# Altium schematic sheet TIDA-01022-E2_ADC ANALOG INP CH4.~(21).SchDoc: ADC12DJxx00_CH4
size 431 x 279 mm; Date: Not shown in title block; ApprovedBy: Not shown in title block; CheckedBy: Not shown in title block; Author: Not shown in title block; CompanyName: Not shown in title block; DrawnBy: Avinash N; Engineer: Not shown in title block; Organization: Not shown in title block; Address1: Not shown in title block; Address2: Not shown in title block; Address3: Not shown in title block; Address4: Not shown in title block; DocumentNumber: 1; Revision: Use project parameter SCH_Rev; SheetNumber: 5; SheetTotal: 26; PageSetup: Record=PageOptions¦CenterHorizontal=True¦CenterVertical=True¦PrintScale=1.00¦XCorrection=1.00¦YCorrection=1.00¦PrintKind=0¦BorderSize=5000000¦LeftOffset=0¦BottomOffset=0¦Orientation=2¦PaperLength=1000¦PaperWidth=1000¦Scale=100¦PaperSource=15¦PrintQuality=600¦MediaType=1¦DitherType=10¦PaperKind=Letter¦PrintScaleMode=1
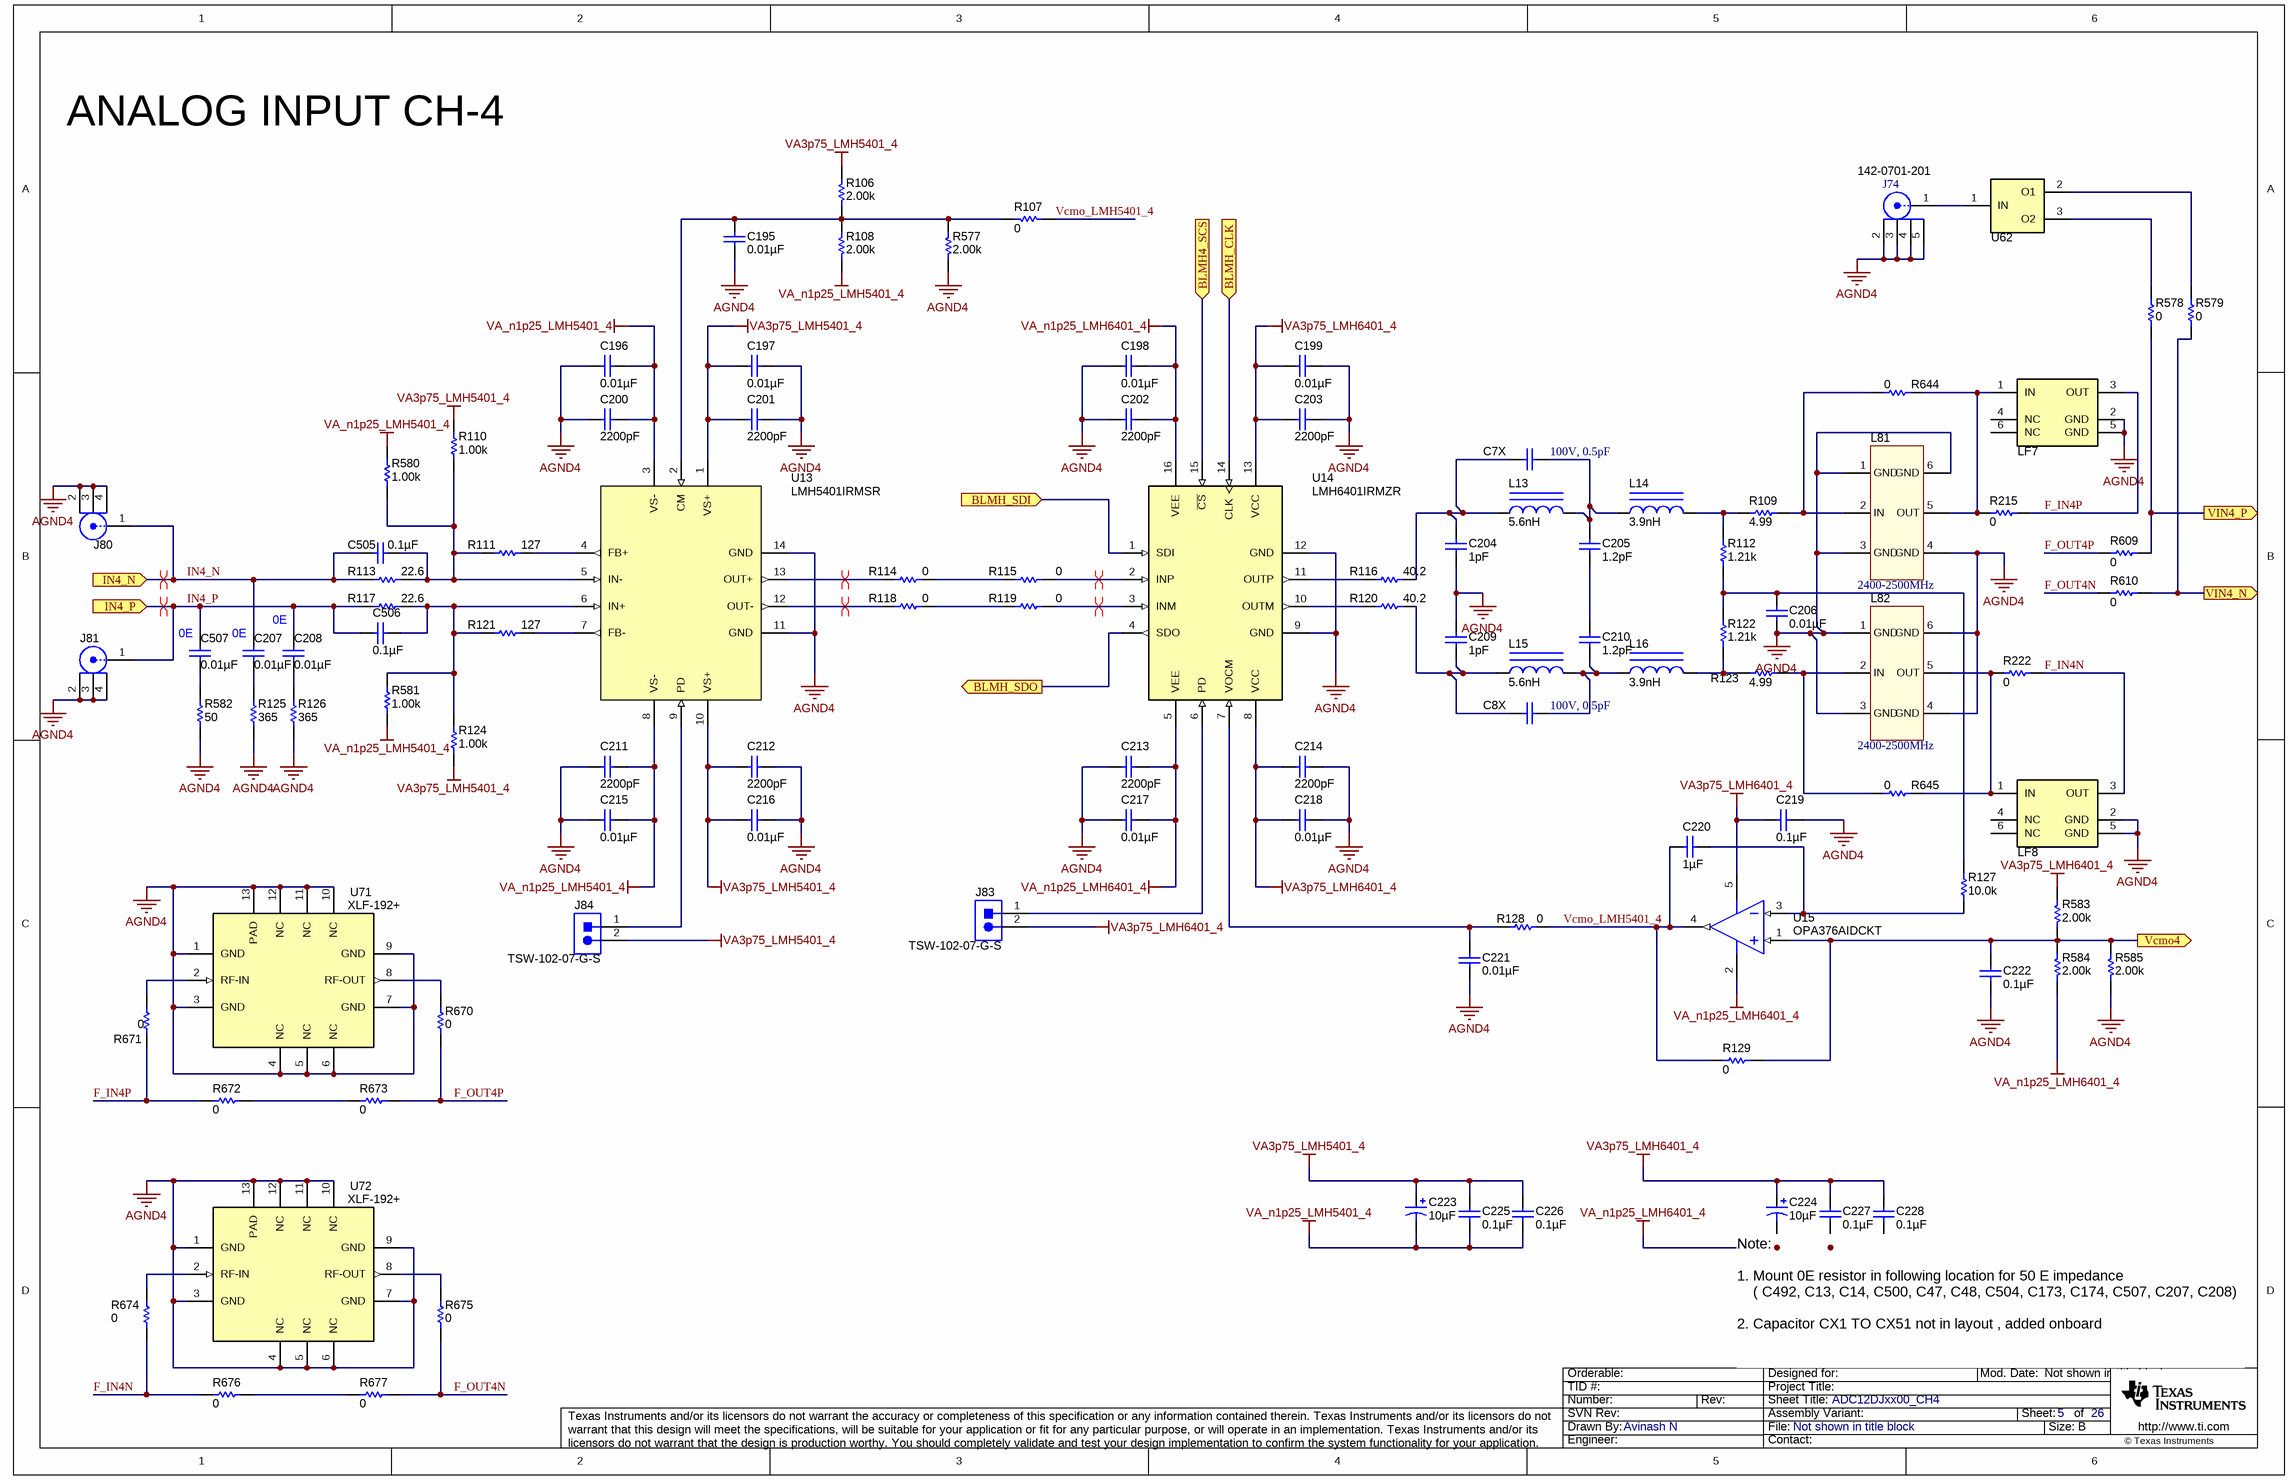
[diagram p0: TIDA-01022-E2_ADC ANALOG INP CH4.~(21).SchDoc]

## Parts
C7X  100V, 0.5pF  [0603_1.6x0.8x0.8mm_Reflow Soldering]
C8X  100V, 0.5pF  [0603_1.6x0.8x0.8mm_Reflow Soldering]
C195  ValueDisplayed: 0.01µF  [0402]  (hidden comment: GRM155R71E103KA01D)
C196  ValueDisplayed: 0.01µF  [0306]  (hidden comment: LLL185R71E103MA01L)
C197  ValueDisplayed: 0.01µF  [0306]  (hidden comment: LLL185R71E103MA01L)
C198  ValueDisplayed: 0.01µF  [0306]  (hidden comment: LLL185R71E103MA01L)
C199  ValueDisplayed: 0.01µF  [0306]  (hidden comment: LLL185R71E103MA01L)
C200  ValueDisplayed: 2200pF  [0306]  (hidden comment: LLL185R71H222MA01L)
C201  ValueDisplayed: 2200pF  [0306]  (hidden comment: LLL185R71H222MA01L)
C202  ValueDisplayed: 2200pF  [0306]  (hidden comment: LLL185R71H222MA01L)
C203  ValueDisplayed: 2200pF  [0306]  (hidden comment: LLL185R71H222MA01L)
C204  ValueDisplayed: 1pF  [0402]  (hidden comment: GRM1555C1H1R0CA01D)
C205  ValueDisplayed: 1.2pF  [0402]  (hidden comment: GRM1555C1H1R2BA01D)
C206  ValueDisplayed: 0.01µF  [0402]  (hidden comment: GRM155R71E103KA01D)
C207  ValueDisplayed: 0.01µF  [0402]  (hidden comment: GRM155R71E103KA01D)
C208  ValueDisplayed: 0.01µF  [0402]  (hidden comment: GRM155R71E103KA01D)
C209  ValueDisplayed: 1pF  [0402]  (hidden comment: GRM1555C1H1R0CA01D)
C210  ValueDisplayed: 1.2pF  [0402]  (hidden comment: GRM1555C1H1R2BA01D)
C211  ValueDisplayed: 2200pF  [0306]  (hidden comment: LLL185R71H222MA01L)
C212  ValueDisplayed: 2200pF  [0306]  (hidden comment: LLL185R71H222MA01L)
C213  ValueDisplayed: 2200pF  [0306]  (hidden comment: LLL185R71H222MA01L)
C214  ValueDisplayed: 2200pF  [0306]  (hidden comment: LLL185R71H222MA01L)
C215  ValueDisplayed: 0.01µF  [0306]  (hidden comment: LLL185R71E103MA01L)
C216  ValueDisplayed: 0.01µF  [0306]  (hidden comment: LLL185R71E103MA01L)
C217  ValueDisplayed: 0.01µF  [0306]  (hidden comment: LLL185R71E103MA01L)
C218  ValueDisplayed: 0.01µF  [0306]  (hidden comment: LLL185R71E103MA01L)
C219  ValueDisplayed: 0.1µF  [0402]  (hidden comment: C1005X5R1A104K050BA)
C220  ValueDisplayed: 1µF  [0603]  (hidden comment: C1608X5R1A105K080AC)
C221  ValueDisplayed: 0.01µF  [0402]  (hidden comment: GRM155R71E103KA01D)
C222  ValueDisplayed: 0.1µF  [0402]  (hidden comment: C1005X5R1A104K050BA)
C223  ValueDisplayed: 10µF  [3216-18]  (hidden comment: TPSA106K010R0900)
C224  ValueDisplayed: 10µF  [3216-18]  (hidden comment: TPSA106K010R0900)
C225  ValueDisplayed: 0.1µF  [0402]  (hidden comment: C1005X5R1A104K050BA)
C226  ValueDisplayed: 0.1µF  [0402]  (hidden comment: C1005X5R1A104K050BA)
C227  ValueDisplayed: 0.1µF  [0402]  (hidden comment: C1005X5R1A104K050BA)
C228  ValueDisplayed: 0.1µF  [0402]  (hidden comment: C1005X5R1A104K050BA)
C505  ValueDisplayed: 0.1µF  [0402]  (hidden comment: GRM155R71C104JA88D)
C506  ValueDisplayed: 0.1µF  [0402]  (hidden comment: GRM155R71C104JA88D)
C507  ValueDisplayed: 0.01µF  [0402]  (hidden comment: GRM155R71E103KA01D)
J74  142-0701-201  [Johnson_142-0701-20x]
J80  142-0771-831  [Johnson_142-0771-831]  (value not drawn)
J81  142-0771-831  [Johnson_142-0771-831]  (value not drawn)
J83  TSW-102-07-G-S  [TSW-102-07-G-S]
J84  TSW-102-07-G-S  [TSW-102-07-G-S]
L13  ValueDisplayed: 5.6nH  [LQW18A]  (hidden comment: LQW18AN5N6D10D)
L14  ValueDisplayed: 3.9nH  [0603HC]  (hidden comment: 0603HC-3N9XJLU)
L15  ValueDisplayed: 5.6nH  [LQW18A]  (hidden comment: LQW18AN5N6D10D)
L16  ValueDisplayed: 3.9nH  [0603HC]  (hidden comment: 0603HC-3N9XJLU)
L81  value 2400-2500MHz  [WE-LPF_0603]  (hidden comment: WE-LPF, 748112024)
L82  value 2400-2500MHz  [WE-LPF_0603]  (hidden comment: WE-LPF, 748112024)
LF7  LFL182G45TC3B746  [FIL_LFL18_TC1]  (value not drawn)
LF8  LFL182G45TC3B746  [FIL_LFL18_TC1]  (value not drawn)
R106  ValueDisplayed: 2.00k  [0402]  (hidden comment: CRCW04022K00FKED)
R107  ValueDisplayed: 0  [0402]  (hidden comment: CRCW04020000Z0ED)
R108  ValueDisplayed: 2.00k  [0402]  (hidden comment: CRCW04022K00FKED)
R109  ValueDisplayed: 4.99  [0402]  (hidden comment: CRCW04024R99FKED)
R110  ValueDisplayed: 1.00k  [0402]  (hidden comment: ERJ-2RKF1001X)
R111  ValueDisplayed: 127  [0402]  (hidden comment: CRCW0402127RFKED)
R112  ValueDisplayed: 1.21k  [0402]  (hidden comment: CRCW04021K21FKED)
R113  ValueDisplayed: 22.6  [0402]  (hidden comment: CRCW040222R6FKED)
R114  ValueDisplayed: 0  [0402]  (hidden comment: CRCW04020000Z0ED)
R115  ValueDisplayed: 0  [0402]  (hidden comment: CRCW04020000Z0ED)
R116  ValueDisplayed: 40.2  [0402]  (hidden comment: CRCW040240R2FKED)
R117  ValueDisplayed: 22.6  [0402]  (hidden comment: CRCW040222R6FKED)
R118  ValueDisplayed: 0  [0402]  (hidden comment: CRCW04020000Z0ED)
R119  ValueDisplayed: 0  [0402]  (hidden comment: CRCW04020000Z0ED)
R120  ValueDisplayed: 40.2  [0402]  (hidden comment: CRCW040240R2FKED)
R121  ValueDisplayed: 127  [0402]  (hidden comment: CRCW0402127RFKED)
R122  ValueDisplayed: 1.21k  [0402]  (hidden comment: CRCW04021K21FKED)
R123  ValueDisplayed: 4.99  [0402]  (hidden comment: CRCW04024R99FKED)
R124  ValueDisplayed: 1.00k  [0402]  (hidden comment: ERJ-2RKF1001X)
R125  ValueDisplayed: 365  [0402]  (hidden comment: CRCW0402365RFKED)
R126  ValueDisplayed: 365  [0402]  (hidden comment: CRCW0402365RFKED)
R127  ValueDisplayed: 10.0k  [0402]  (hidden comment: CRCW040210K0FKED)
R128  ValueDisplayed: 0  [0402]  (hidden comment: CRCW04020000Z0ED)
R129  ValueDisplayed: 0  [0402]  (hidden comment: CRCW04020000Z0ED)
R215  ValueDisplayed: 0  [0402_FILTER]  (hidden comment: CRCW04020000Z0ED)
R222  ValueDisplayed: 0  [0402_FILTER]  (hidden comment: CRCW04020000Z0ED)
R577  ValueDisplayed: 2.00k  [0402]  (hidden comment: CRCW04022K00FKED)
R578  ValueDisplayed: 0  [0201_adc]  (hidden comment: CRCW02010000Z0ED)
R579  ValueDisplayed: 0  [0201_adc]  (hidden comment: CRCW02010000Z0ED)
R580  ValueDisplayed: 1.00k  [0402]  (hidden comment: ERJ-2RKF1001X)
R581  ValueDisplayed: 1.00k  [0402]  (hidden comment: ERJ-2RKF1001X)
R582  ValueDisplayed: 50  [0402]  (hidden comment: FC0402E50R0BTBST1)
R583  ValueDisplayed: 2.00k  [0402]  (hidden comment: CRCW04022K00FKED)
R584  ValueDisplayed: 2.00k  [0402]  (hidden comment: CRCW04022K00FKED)
R585  ValueDisplayed: 2.00k  [0402]  (hidden comment: CRCW04022K00FKED)
R609  ValueDisplayed: 0  [0201_adc]  (hidden comment: CRCW02010000Z0ED)
R610  ValueDisplayed: 0  [0201_adc]  (hidden comment: CRCW02010000Z0ED)
R644  ValueDisplayed: 0  [0402_FILTER]  (hidden comment: CRCW04020000Z0ED)
R645  ValueDisplayed: 0  [0402_FILTER]  (hidden comment: CRCW04020000Z0ED)
R670  ValueDisplayed: 0  [0201_adc]  (hidden comment: CRCW02010000Z0ED)
R671  ValueDisplayed: 0  [0201_adc]  (hidden comment: CRCW02010000Z0ED)
R672  ValueDisplayed: 0  [0201_adc]  (hidden comment: CRCW02010000Z0ED)
R673  ValueDisplayed: 0  [0201_adc]  (hidden comment: CRCW02010000Z0ED)
R674  ValueDisplayed: 0  [0201_adc]  (hidden comment: CRCW02010000Z0ED)
R675  ValueDisplayed: 0  [0201_adc]  (hidden comment: CRCW02010000Z0ED)
R676  ValueDisplayed: 0  [0201_adc]  (hidden comment: CRCW02010000Z0ED)
R677  ValueDisplayed: 0  [0201_adc]  (hidden comment: CRCW02010000Z0ED)
U13  LMH5401IRMSR  [RMS0014A]
U14  LMH6401IRMZR  [RMZ0016A]
U15  OPA376AIDCKT  [DCK0005A_N]
U62  BAL-0006SMG  [Marki_BAL-0006SMG]  (value not drawn)
U71  XLF-192+  [DQ1225]
U72  XLF-192+  [DQ1225]

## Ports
BLMH4_SCS (in), BLMH_CLK (in), BLMH_SDI (in), BLMH_SDO (out), IN4_N (in), IN4_P (in), Vcmo4 (out), VIN4_N (out), VIN4_P (out)

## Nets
AGND4: C195.2 C196.1 C197.1 C198.1 C199.1 C200.2 C201.2 C202.2 C203.2 C204.2 C206.2 C209.2 C211.2 C212.2 C213.2 C214.2 C215.1 C216.1 C217.1 C218.1 C219.1 C221.2 C222.2 J74.2 J74.3 J74.4 J74.5 J80.2 J80.3 J80.4 J81.2 J81.3 J81.4 L81.1(GND) L81.3(GND) L81.4(GND) L81.6(GND) L82.1(GND) L82.3(GND) L82.4(GND) L82.6(GND) LF7.2(GND) LF7.5(GND) LF8.2(GND) LF8.5(GND) R125.1 R126.1 R577.1 R582.1 R585.1 U13.11(GND) U13.14(GND) U14.9(GND) U14.12(GND) U71.1(GND) U71.3(GND) U71.4(NC) U71.5(NC) U71.6(NC) U71.7(GND) U71.9(GND) U71.10(NC) U71.11(NC) U71.12(NC) U71.13(PAD) U72.1(GND) U72.3(GND) U72.4(NC) U72.5(NC) U72.6(NC) U72.7(GND) U72.9(GND) U72.10(NC) U72.11(NC) U72.12(NC) U72.13(PAD)
VA3p75_LMH5401_4: C197.2 C201.1 C212.1 C216.2 C223.1(+) C225.1 C226.1 J84.2 R106.2 R110.2 R124.1 U13.1(VS+) U13.10(VS+)
VA3p75_LMH6401_4: C199.2 C203.1 C214.1 C218.2 C219.2 C224.1(+) C227.1 C228.1 J83.2 R583.2 U14.8(VCC) U14.13(VCC) U15.5(V+)
VA_n1p25_LMH5401_4: C196.2 C200.1 C211.1 C215.2 C223.2(-) C225.2 C226.2 R108.1 R580.2 R581.2 U13.3(VS-) U13.8(VS-)
VA_n1p25_LMH6401_4: C198.2 C202.1 C213.1 C217.2 C224.2(-) C227.2 C228.2 R584.1 U14.5(VEE) U14.16(VEE) U15.2(V-)
BLMH4_SCS: U14.15(~{CS}) ; port BLMH4_SCS
BLMH_CLK: U14.14(CLK) ; port BLMH_CLK
BLMH_SDI: U14.1(SDI) ; port BLMH_SDI
BLMH_SDO: U14.4(SDO) ; port BLMH_SDO
F_IN4N: LF8.3(OUT) R222.2 R674.1 R676.1
F_IN4P: LF7.3(OUT) R215.2 R671.1 R672.1
F_OUT4N: R610.1 R675.1 R677.2
F_OUT4P: R609.1 R670.1 R673.2
IN4_N: C207.1 C505.2 J80.1 R113.1 ; port IN4_N
IN4_P: C208.1 C506.1 C507.1 J81.1 R117.1 ; port IN4_P
Vcmo4: C222.1 R129.1 R583.1 R584.2 R585.2 U15.1(IN+) ; port Vcmo4
Vcmo_LMH5401_4: C220.1 R107.2 R128.1 R129.2 U15.4(OUT)
VIN4_N: R579.2 R610.2 ; port VIN4_N
VIN4_P: R578.2 R609.2 ; port VIN4_P
NetC7X_1: C7X.1 C204.1 L13.1 R116.1
NetC7X_2: C7X.2 C205.1 L13.2 L14.1
NetC8X_1: C8X.1 C209.1 L15.1 R120.1
NetC8X_2: C8X.2 C210.1 L15.2 L16.1
NetC195_1: C195.1 R106.1 R107.1 R108.2 R577.2 U13.2(CM)
NetC205_2: C205.2 C210.2
NetC206_1: C206.1 R112.1 R122.1 R127.2
NetC207_2: C207.2 R125.2
NetC208_2: C208.2 R126.2
NetC220_2: C220.2 R127.1 U15.3(IN-)
NetC221_1: C221.1 R128.2 U14.7(VOCM)
NetC505_1: C505.1 R110.1 R111.1 R113.2 R580.1 U13.5(IN-)
NetC506_2: C506.2 R117.2 R121.1 R124.2 R581.1 U13.6(IN+)
NetC507_2: C507.2 R582.2
NetJ74_1: J74.1 U62.1(IN)
NetJ83_1: J83.1 U14.6(PD)
NetJ84_1: J84.1 U13.9(PD)
NetL14_2: L14.2 R109.1 R112.2
NetL16_2: L16.2 R122.2 R123.1
NetL81_2: L81.2(IN) R109.2 R644.1
NetL81_5: L81.5(OUT) LF7.1(IN) R215.1 R644.2
NetL82_2: L82.2(IN) R123.2 R645.1
NetL82_5: L82.5(OUT) LF8.1(IN) R222.1 R645.2
NetR111_2: R111.2 U13.4(FB+)
NetR114_1: R114.1 U13.13(OUT+)
NetR114_2: R114.2 R115.2
NetR115_1: R115.1 U14.2(INP)
NetR116_2: R116.2 U14.11(OUTP)
NetR118_1: R118.1 U13.12(OUT-)
NetR118_2: R118.2 R119.2
NetR119_1: R119.1 U14.3(INM)
NetR120_2: R120.2 U14.10(OUTM)
NetR121_2: R121.2 U13.7(FB-)
NetR578_1: R578.1 U62.3(O2)
NetR579_1: R579.1 U62.2(O1)
NetR670_2: R670.2 U71.8(RF-OUT)
NetR671_2: R671.2 U71.2(RF-IN)
NetR672_2: R672.2 R673.1
NetR674_2: R674.2 U72.2(RF-IN)
NetR675_2: R675.2 U72.8(RF-OUT)
NetR676_2: R676.2 R677.1

Not connected (* = marked no-connect by the designer): LF7 4(NC) 6(NC); LF8 4(NC) 6(NC)

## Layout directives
differential pair: IN4_N, IN4_P, NetR114_1, NetR115_1, NetR118_1, NetR119_1

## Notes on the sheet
- ANALOG INPUT CH-4
- (near C507) 0E
- (near C207) 0E
- 0E
- Note:
  1. Mount 0E resistor in following location for 50 E impedance
  ( C492, C13, C14, C500, C47, C48, C504, C173, C174, C507, C207, C208)
  2. Capacitor CX1 TO CX51 not in layout , added onboard

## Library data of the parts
C7X C8X = 885012006086: WCAP-CSGP Ceramic Capacitors, 0603, NP0, 100V, 0.5pF; Rated Voltage: 100V DC
C195 C206-C208 C221 C507 = GRM155R71E103KA01D: CAP, CERM, 0.01 µF, 25 V, +/- 10%, X7R, 0402; Manufacturer: MuRata; Polarized: N; CompType: Capacitor; Value: 0.01uF; U/M: EA; Cap_F: 0.00000001; Tolerance_%: 10; Value1: Unknown; VDC_V: 25; Value2: 25V; TaMin_C: -55; TaMax_C: 125; SizeArea_mm2: 0.5; SizeAreaWB_mm2: 3; SizeX_mm: 1; SizeZ_mm: 0.6; AEC Category: Q200
C196-C199 C215-C218 = LLL185R71E103MA01L: CAP, CERM, 0.01 µF, 25 V, +/- 20%, X7R, 0306; Manufacturer: MuRata; Polarized: N; CompType: Capacitor; Value: 0.01uF; U/M: EA; Cap_F: 0.00000001; Tolerance_%: 20; Value1: Unknown; VDC_V: 25; Value2: 25V; TaMin_C: -55; TaMax_C: 125; SizeArea_mm2: 1.28; SizeAreaWB_mm2: 4.68; SizeX_mm: 0.8; SizeY_mm: 1.6; SizeZ_mm: 0.6; AEC Category: Q200
C200-C203 C211-C214 = LLL185R71H222MA01L: CAP, CERM, 2200 pF, 50 V, +/- 20%, X7R, 0306; Manufacturer: MuRata; Polarized: N; CompType: Capacitor; Value: 2200pF; U/M: EA; Cap_F: 0.0000000022; Tolerance_%: 20; Value1: Unknown; VDC_V: 50; Value2: 50V; TaMin_C: -55; TaMax_C: 125; SizeArea_mm2: 1.28; SizeAreaWB_mm2: 4.68; SizeX_mm: 0.8; SizeY_mm: 1.6; SizeZ_mm: 0.6; AEC Category: Q200
C204 C209 = GRM1555C1H1R0CA01D: CAP, CERM, 1 pF, 50 V, +/- 5%, C0G/NP0, 0402; Manufacturer: MuRata; Polarized: N; CompType: Capacitor; Value: 1pF; U/M: EA; Cap_F: 0.000000000001; Tolerance_%: 5; Value1: Unknown; VDC_V: 50; Value2: 50V; TaMin_C: -55; TaMax_C: 125; SizeArea_mm2: 0.5; SizeAreaWB_mm2: 3; SizeX_mm: 1; SizeZ_mm: 0.6; AEC Category: Q200
C205 C210 = GRM1555C1H1R2BA01D: CAP, CERM, 1.2 pF, 50 V, +/- 8.3%, C0G/NP0, 0402; Manufacturer: MuRata; Polarized: N; CompType: Capacitor; Value: 1.2pF; U/M: EA; Cap_F: 0.0000000000012; Tolerance_%: 8.3; Value1: Unknown; VDC_V: 50; Value2: 50V; TaMin_C: -55; TaMax_C: 125; SizeArea_mm2: 0.5; SizeAreaWB_mm2: 3; SizeX_mm: 1; SizeZ_mm: 0.6; AEC Category: Q200
C219 C222 C225-C228 = C1005X5R1A104K050BA: CAP, CERM, 0.1 µF, 10 V, +/- 10%, X5R, 0402; Manufacturer: TDK; Polarized: N; CompType: Capacitor; Value: 0.1uF; U/M: EA; Cap_F: 0.0000001; Tolerance_%: 10; Value1: Unknown; Value2: 10V; TaMin_C: -55; TaMax_C: 85; SizeArea_mm2: 0.5; SizeAreaWB_mm2: 3; SizeX_mm: 1; SizeZ_mm: 0.6; AEC Category: Q200
C220 = C1608X5R1A105K080AC: CAP, CERM, 1 µF, 10 V, +/- 10%, X5R, 0603; Manufacturer: TDK; Polarized: N; CompType: Capacitor; Value: 1uF; U/M: EA; Cap_F: 0.000001; Tolerance_%: 10; Value1: Unknown; Value2: 10V; TaMin_C: -55; TaMax_C: 85; SizeArea_mm2: 1.28; SizeAreaWB_mm2: 4.68; SizeX_mm: 1.6; SizeY_mm: 0.8; SizeZ_mm: 1; AEC Category: Q200
C223 C224 = TPSA106K010R0900: CAP, TA, 10 µF, 10 V, +/- 10%, 0.9 ohm, SMD; Manufacturer: AVX; Polarized: Y; CompType: Capacitor; Value: 10uF; U/M: EA; Cap_F: 0.00001; Tolerance_%: 10; Value1: 0.9 ohm; Value2: 10V; ESR_ohm: 0.9; IRMS_A: 0.26; TaMin_C: -55; TaMax_C: 125; Cap_Case: A; SizeAreaWB_mm2: 10.92; SizeArea_mm2: 5.12; SizeX_mm: 3.2; SizeY_mm: 1.6; SizeZ_mm: 1.8; AEC Category: Q200
C505 C506 = GRM155R71C104JA88D: CAP, CERM, 0.1 µF, 16 V, +/- 5%, X7R, 0402; Manufacturer: MuRata; Polarized: N; CompType: Capacitor; Value: 0.1uF; U/M: EA; Cap_F: 0.0000001; Tolerance_%: 5; Value1: Unknown; VDC_V: 16; Value2: 16V; TaMin_C: -55; TaMax_C: 125; SizeArea_mm2: 0.5; SizeAreaWB_mm2: 3; SizeX_mm: 1; SizeZ_mm: 0.6; AEC Category: Q200
J74 = 142-0701-201: Connector, TH, SMA; Manufacturer: Emerson Network Power; SymbolCreator: X0208326
J80 J81 = 142-0771-831: JACK, SMA, 50 Ohm, Gold, Edge Mount; Manufacturer: Johnson; SymbolCreator: Altium; Gender: Female; Voltage_V: 170
J83 J84 = TSW-102-07-G-S: Header, 100mil, 2x1, Gold, TH; Manufacturer: Samtec; SymbolCreator: a0412235; Pitch_mm: 2.54; Gender: Male; Shrouded: N; Row_Count: 1; Current_A: 6.3; Voltage_V: 550; Cert_CSA: Y
L13 L15 = LQW18AN5N6D10D: Inductor, Wirewound, 5.6 nH, 0.9 A, 0.045 ohm, SMD; Manufacturer: MuRata; Value: 5.6nH; Ind_H: 5.6E-9; Imax_A: 0.9; Irms: 0.9A @ C rise; DCR_ohm: 0.045; Value2: 0.9A; SizeAreaWB_mm2: 4.68; SizeArea_mm2: 1.28; SizeX_mm: 1.6; SizeY_mm: 0.8; SizeZ_mm: 1; AEC Category: Q200; AEC Qualified: N
L14 L16 = 0603HC-3N9XJLU: Inductor, Wirewound, Ceramic, 3.9 nH, 2.2 A, 0.054 ohm, SMD; Manufacturer: Coilcraft; Value: 3.9nH; Ind_H: 3.9E-9; Imax_A: 2.2; Irms: 2.4A @ 20C rise; DCR_ohm: 0.054; Value2: 2.2A; SizeAreaWB_mm2: 5.936; SizeArea_mm2: 2.016; SizeX_mm: 1.8; SizeY_mm: 1.12; SizeZ_mm: 1.02; AEC Category: Q200
L81 L82 = WE-LPF, 748112024: WE-LPF Multilayer Chip Low-Pass Filter, size 0603, 2400-2500MHz
LF7 LF8 = LFL182G45TC3B746: Filter for Communication Equipment, SMD; Manufacturer: MuRata; SymbolCreator: Altium; SizeAreaWB_mm2: 4.68; SizeArea_mm2: 1.28; SizeX_mm: 1.6; SizeY_mm: 0.8; SizeZ_mm: 0.7
R106 R108 R577 R583-R585 = CRCW04022K00FKED: RES, 2.00 k, 1%, 0.063 W, 0402; Manufacturer: Vishay-Dale; CompType: Resistor; Value: 2.00k; Res_ohm: 2000; Value_Code: 2k00; Tolerance_%: 1; Power_W: 0.063; Value2: 0.063W; VDC_V: 50; TempCo: 100 ppm/C; SizeArea_mm2: 0.5; SizeZ_mm: 0.6; EIA_Code: E96; U/M: EA; AEC Category: Q200
R107 R114 R115 R118 R119 R128 R129 R215 R222 R644 R645 = CRCW04020000Z0ED: RES, 0, 5%, 0.063 W, 0402; Manufacturer: Vishay-Dale; CompType: Resistor; Value: 0; Value_Code: 0000; Tolerance_%: 5; Power_W: 0.063; Value2: 0.063W; VDC_V: 50; TempCo: 200 ppm/C; SizeArea_mm2: 0.5; SizeX_mm: 1; SizeZ_mm: 0.6; EIA_Code: E24; U/M: EA; AEC Category: Q200
R109 R123 = CRCW04024R99FKED: RES, 4.99, 1%, 0.063 W, 0402; Manufacturer: Vishay-Dale; CompType: Resistor; Value: 4.99; Value_Code: 4R99; Tolerance_%: 1; Power_W: 0.063; Value2: 0.063W; VDC_V: 50; TempCo: 100 ppm/C; SizeArea_mm2: 0.5; SizeZ_mm: 0.6; EIA_Code: E96; U/M: EA; AEC Category: Q200
R110 R124 R580 R581 = ERJ-2RKF1001X: RES, 1.00 k, 1%, 0.1 W, 0402; Manufacturer: Panasonic; CompType: Resistor; Value: 1.00k; Res_ohm: 1000; Value_Code: 1k00; Tolerance_%: 1; Power_W: 0.1; Value2: 0.1W; VDC_V: 50; TempCo: 100 ppm/C; SizeArea_mm2: 0.5; SizeZ_mm: 0.6; EIA_Code: E96; U/M: EA; AEC Category: Q200
R111 R121 = CRCW0402127RFKED: RES, 127, 1%, 0.063 W, 0402; Manufacturer: Vishay-Dale; CompType: Resistor; Value: 127; Value_Code: 127R; Tolerance_%: 1; Power_W: 0.063; Value2: 0.063W; VDC_V: 50; TempCo: 100 ppm/C; SizeArea_mm2: 0.5; SizeZ_mm: 0.6; EIA_Code: E96; U/M: EA; AEC Category: Q200
R112 R122 = CRCW04021K21FKED: RES, 1.21 k, 1%, 0.063 W, 0402; Manufacturer: Vishay-Dale; CompType: Resistor; Value: 1.21k; Res_ohm: 1210; Value_Code: 1k21; Tolerance_%: 1; Power_W: 0.063; Value2: 0.063W; VDC_V: 50; TempCo: 100 ppm/C; SizeArea_mm2: 0.5; SizeZ_mm: 0.6; EIA_Code: E96; U/M: EA; AEC Category: Q200
R113 R117 = CRCW040222R6FKED: RES, 22.6, 1%, 0.063 W, 0402; Manufacturer: Vishay-Dale; CompType: Resistor; Value: 22.6; Value_Code: 22R6; Tolerance_%: 1; Power_W: 0.063; Value2: 0.063W; VDC_V: 50; TempCo: 100 ppm/C; SizeArea_mm2: 0.5; SizeZ_mm: 0.6; EIA_Code: E96; U/M: EA; AEC Category: Q200
R116 R120 = CRCW040240R2FKED: RES, 40.2, 1%, 0.063 W, 0402; Manufacturer: Vishay-Dale; CompType: Resistor; Value: 40.2; Value_Code: 40R2; Tolerance_%: 1; Power_W: 0.063; Value2: 0.063W; VDC_V: 50; TempCo: 100 ppm/C; SizeArea_mm2: 0.5; SizeZ_mm: 0.6; EIA_Code: E96; U/M: EA; AEC Category: Q200
R125 R126 = CRCW0402365RFKED: RES, 365, 1%, 0.063 W, 0402; Manufacturer: Vishay-Dale; CompType: Resistor; Value: 365; Value_Code: 365R; Tolerance_%: 1; Power_W: 0.063; Value2: 0.063W; VDC_V: 50; TempCo: 100 ppm/C; SizeArea_mm2: 0.5; SizeZ_mm: 0.6; EIA_Code: E96; U/M: EA; AEC Category: Q200
R127 = CRCW040210K0FKED: RES, 10.0 k, 1%, 0.063 W, 0402; Manufacturer: Vishay-Dale; CompType: Resistor; Value: 10.0k; Res_ohm: 10000; Value_Code: 10k0; Tolerance_%: 1; Power_W: 0.063; Value2: 0.063W; VDC_V: 50; TempCo: 100 ppm/C; SizeArea_mm2: 0.5; SizeZ_mm: 0.6; EIA_Code: E96; U/M: EA; AEC Category: Q200
R578 R579 R609 R610 R670-R677 = CRCW02010000Z0ED: RES, 0, 5%, 0.05 W, 0201; Manufacturer: Vishay-Dale; CompType: Resistor; Value: 0; Value_Code: 0000; Tolerance_%: 5; Power_W: 0.05; Value2: 0.05W; TempCo: ppm/C; SizeArea_mm2: 0.18; SizeX_mm: 0.6; SizeY_mm: 0.3; SizeZ_mm: 0.26; EIA_Code: E24; U/M: EA; AEC Category: Q200; AEC Qualified: N
R582 = FC0402E50R0BTBST1: RES, 50, 0.1%, 0.5 W, 0402; Manufacturer: Vishay Thin Film; CompType: Resistor; Value: 50; Value_Code: 50R0; Tolerance_%: 0.1; Power_W: 0.5; Value2: 0.5W; TempCo: 0.1 ppm/C; SizeX_mm: 1; SizeZ_mm: 0.6; U/M: EA; AEC Category: Q200; AEC Qualified: N
U13 = LMH5401IRMSR: 8GHz Ultra Wideband Fully Differential Amplifier, RMS0014A (UQFN-14); Alternate PartNumber: LMH5401IRMST; Manufacturer: Texas Instruments; SymbolCreator: Altium; SizeArea_mm2: 6.25; SizeAreaWB_mm2: 12.25; SizeX_mm: 2.5; SizeZ_mm: 0.6; CompType: IC; U/M: EA
U14 = LMH6401IRMZR: 4.5 GHz Ultra Wideband Digital Variable Gain Amplifier, RMZ0016A (UQFN-HR-16); Alternate PartNumber: LMH6401IRMZT; Manufacturer: Texas Instruments; SymbolCreator: Altium; SizeArea_mm2: 9; SizeAreaWB_mm2: 16; SizeX_mm: 3; SizeZ_mm: 0.65; CompType: IC; U/M: EA
U15 = OPA376AIDCKT: Precision, Low Noise, Low Iq Operational Amplifier, 2.2 to 5.5 V, -40 to 125 degC, 5-pin SOT23 (DCK0005A), Green (RoHS & no Sb/Br); Manufacturer: Texas Instruments; Alternate PartNumber: Equivalent; CMRR(Min)(dB): 76; IIB(Max)(pA): 10; Iq per channel(Max)(mA): 0.95; Number of Channels: 1; Offset Drift(Typ)(uV/C): 0.32; Slew Rate(Typ)(V/us): 2; Sub Family: Low Input Bias Current Amp (<=10pA), Low Noise Amp (<=10nV/rtHz), Low Offset Voltage Amplifier (<=500uV), Low Supply Voltage Amplifier (<=2.7V), Precision Amplifier; Total Supply Voltage(Max)(+5V is 5, +/-5V is 10): 5.5; Total Supply Voltage(Min)(+5V is 5, +/-5V is 10): 2.2; Vio (25C)(Max)(mV): 0.025; Vn at 1kHz(Typ)(nV/rtHz): 7.5
U62 = BAL-0006SMG: Broadband Balun, 500 kHz to 6 GHz; Manufacturer: Marki Microwave; SymbolCreator: Altium; SizeAreaWB_mm2: 102.6169; SizeArea_mm2: 66.0969; SizeX_mm: 8.13; SizeZ_mm: 3.94
U71 U72 = CMP-0077784-1: Reflectionless Low Pass Filter, SMD; Manufacturer: Minicircuits; SizeArea_mm2: 9; SizeAreaWB_mm2: 16; SizeY_mm: 3; SizeZ_mm: 0.89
